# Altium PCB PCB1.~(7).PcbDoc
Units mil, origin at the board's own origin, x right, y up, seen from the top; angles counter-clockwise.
Board outline 2756 x 2756 mil, 4 copper layers (Top Layer, Internal Plane 1, Internal Plane 2, Bottom Layer), stack 18.2 mil thick; 11 components, 12 nets, 54 pads, 0 vias.
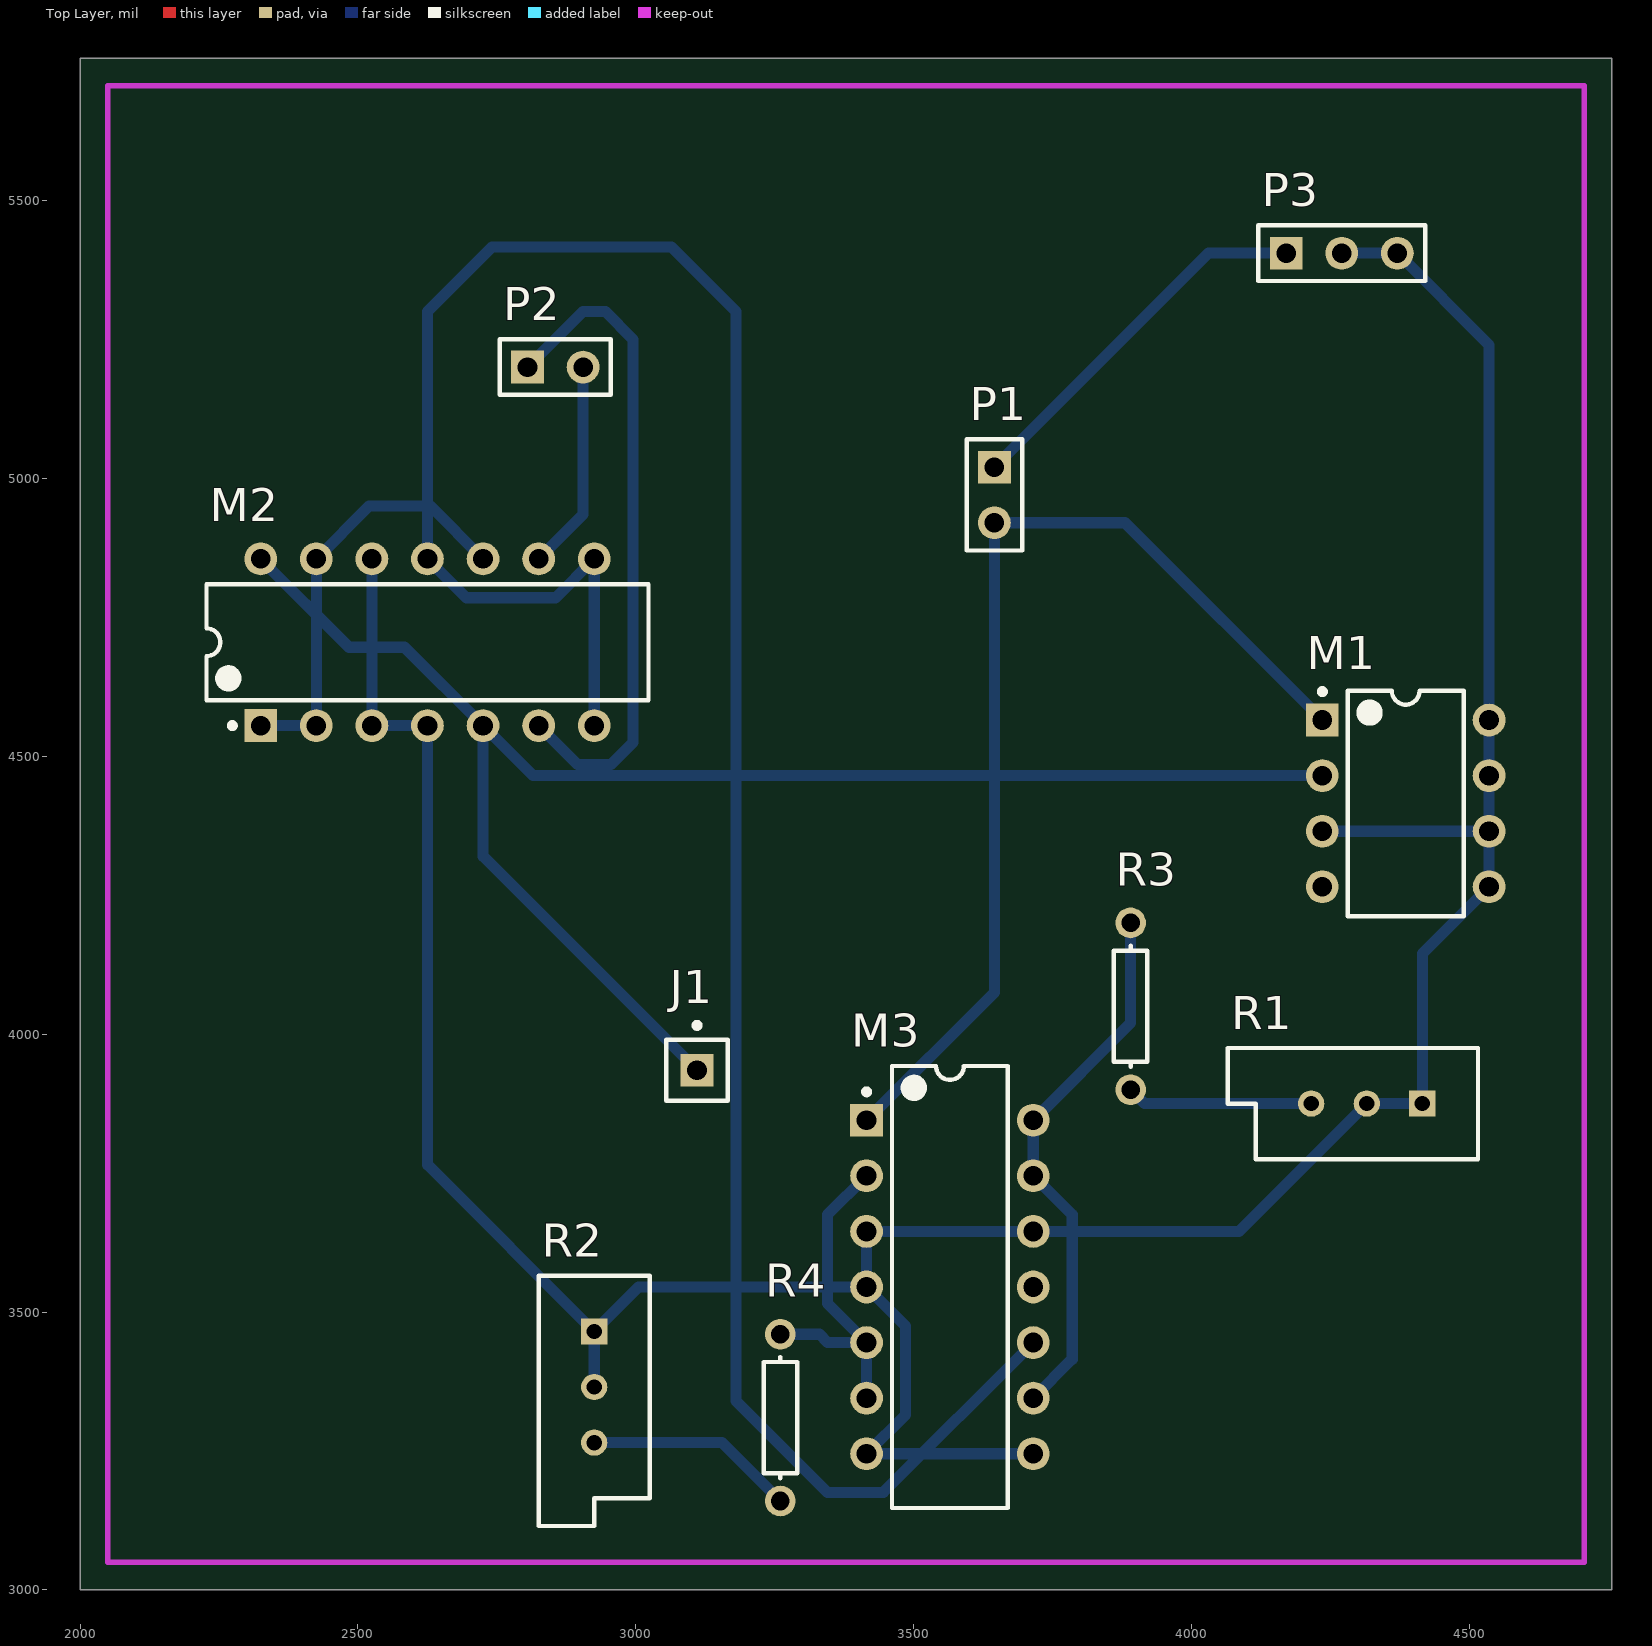
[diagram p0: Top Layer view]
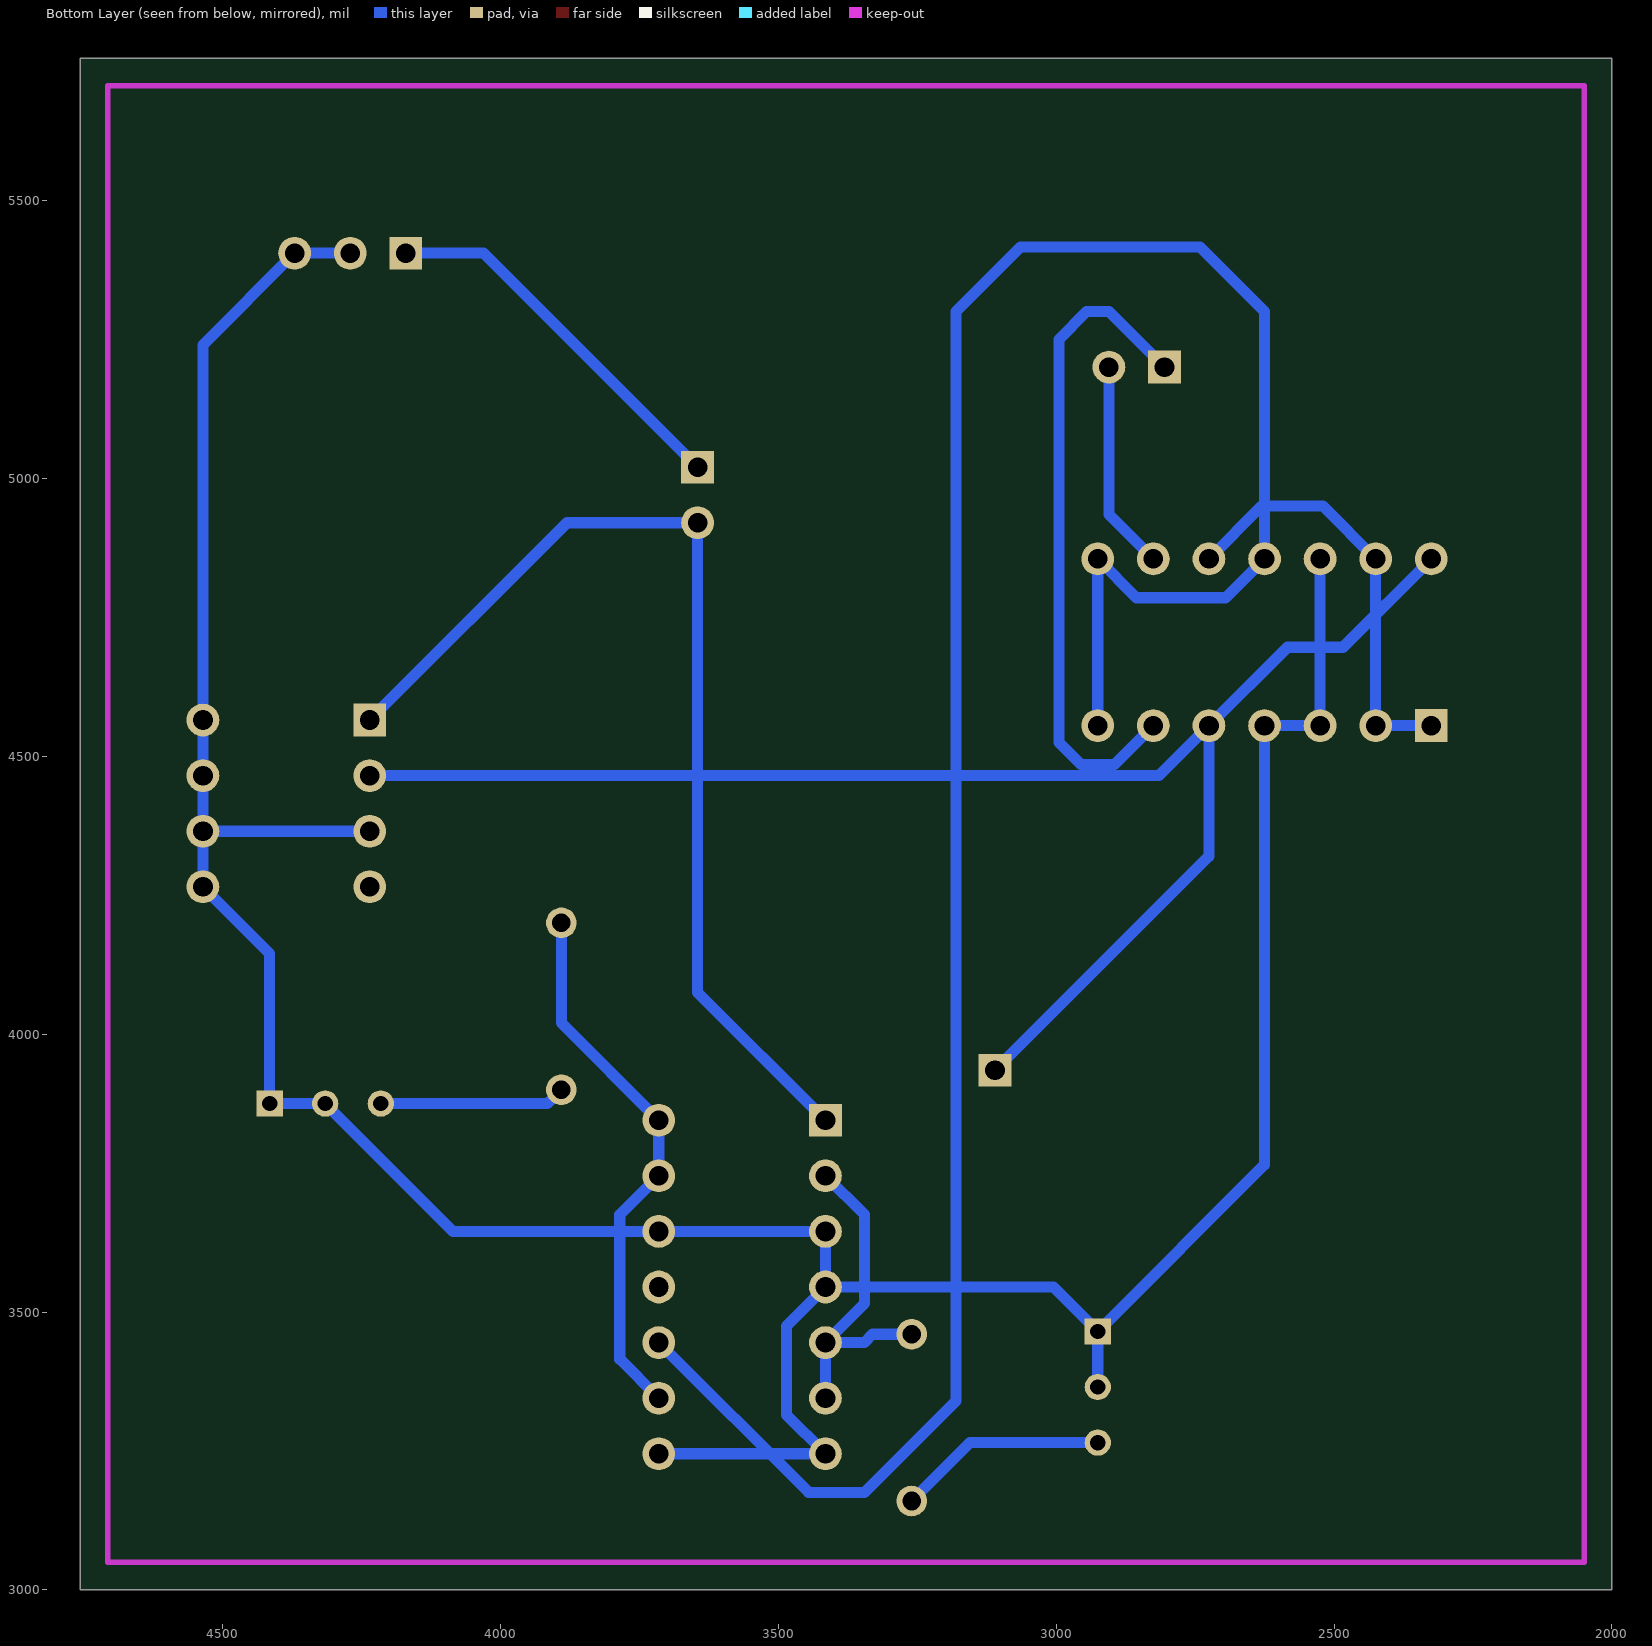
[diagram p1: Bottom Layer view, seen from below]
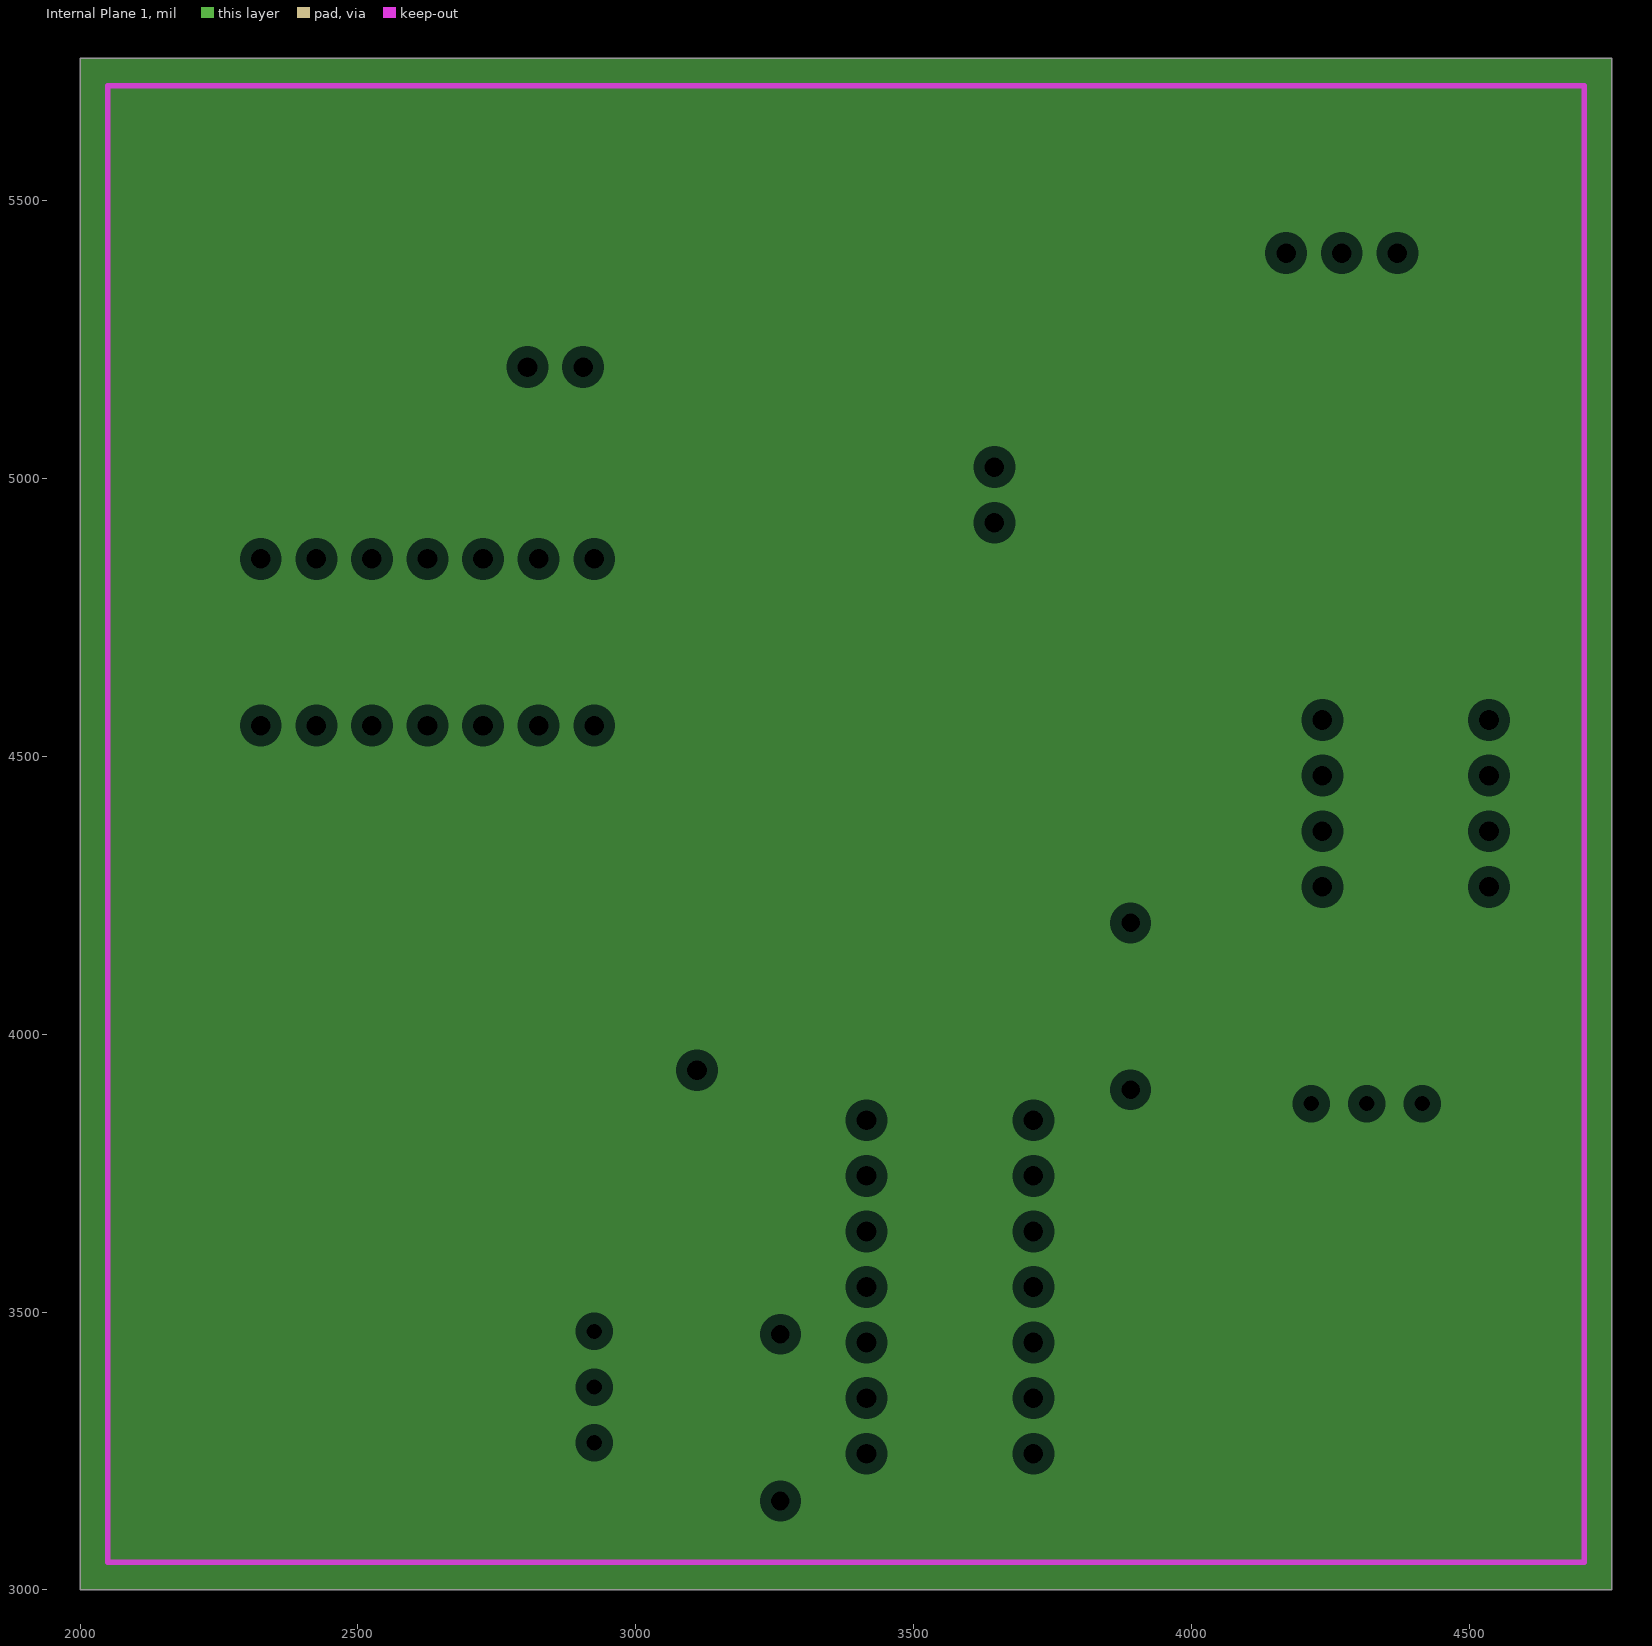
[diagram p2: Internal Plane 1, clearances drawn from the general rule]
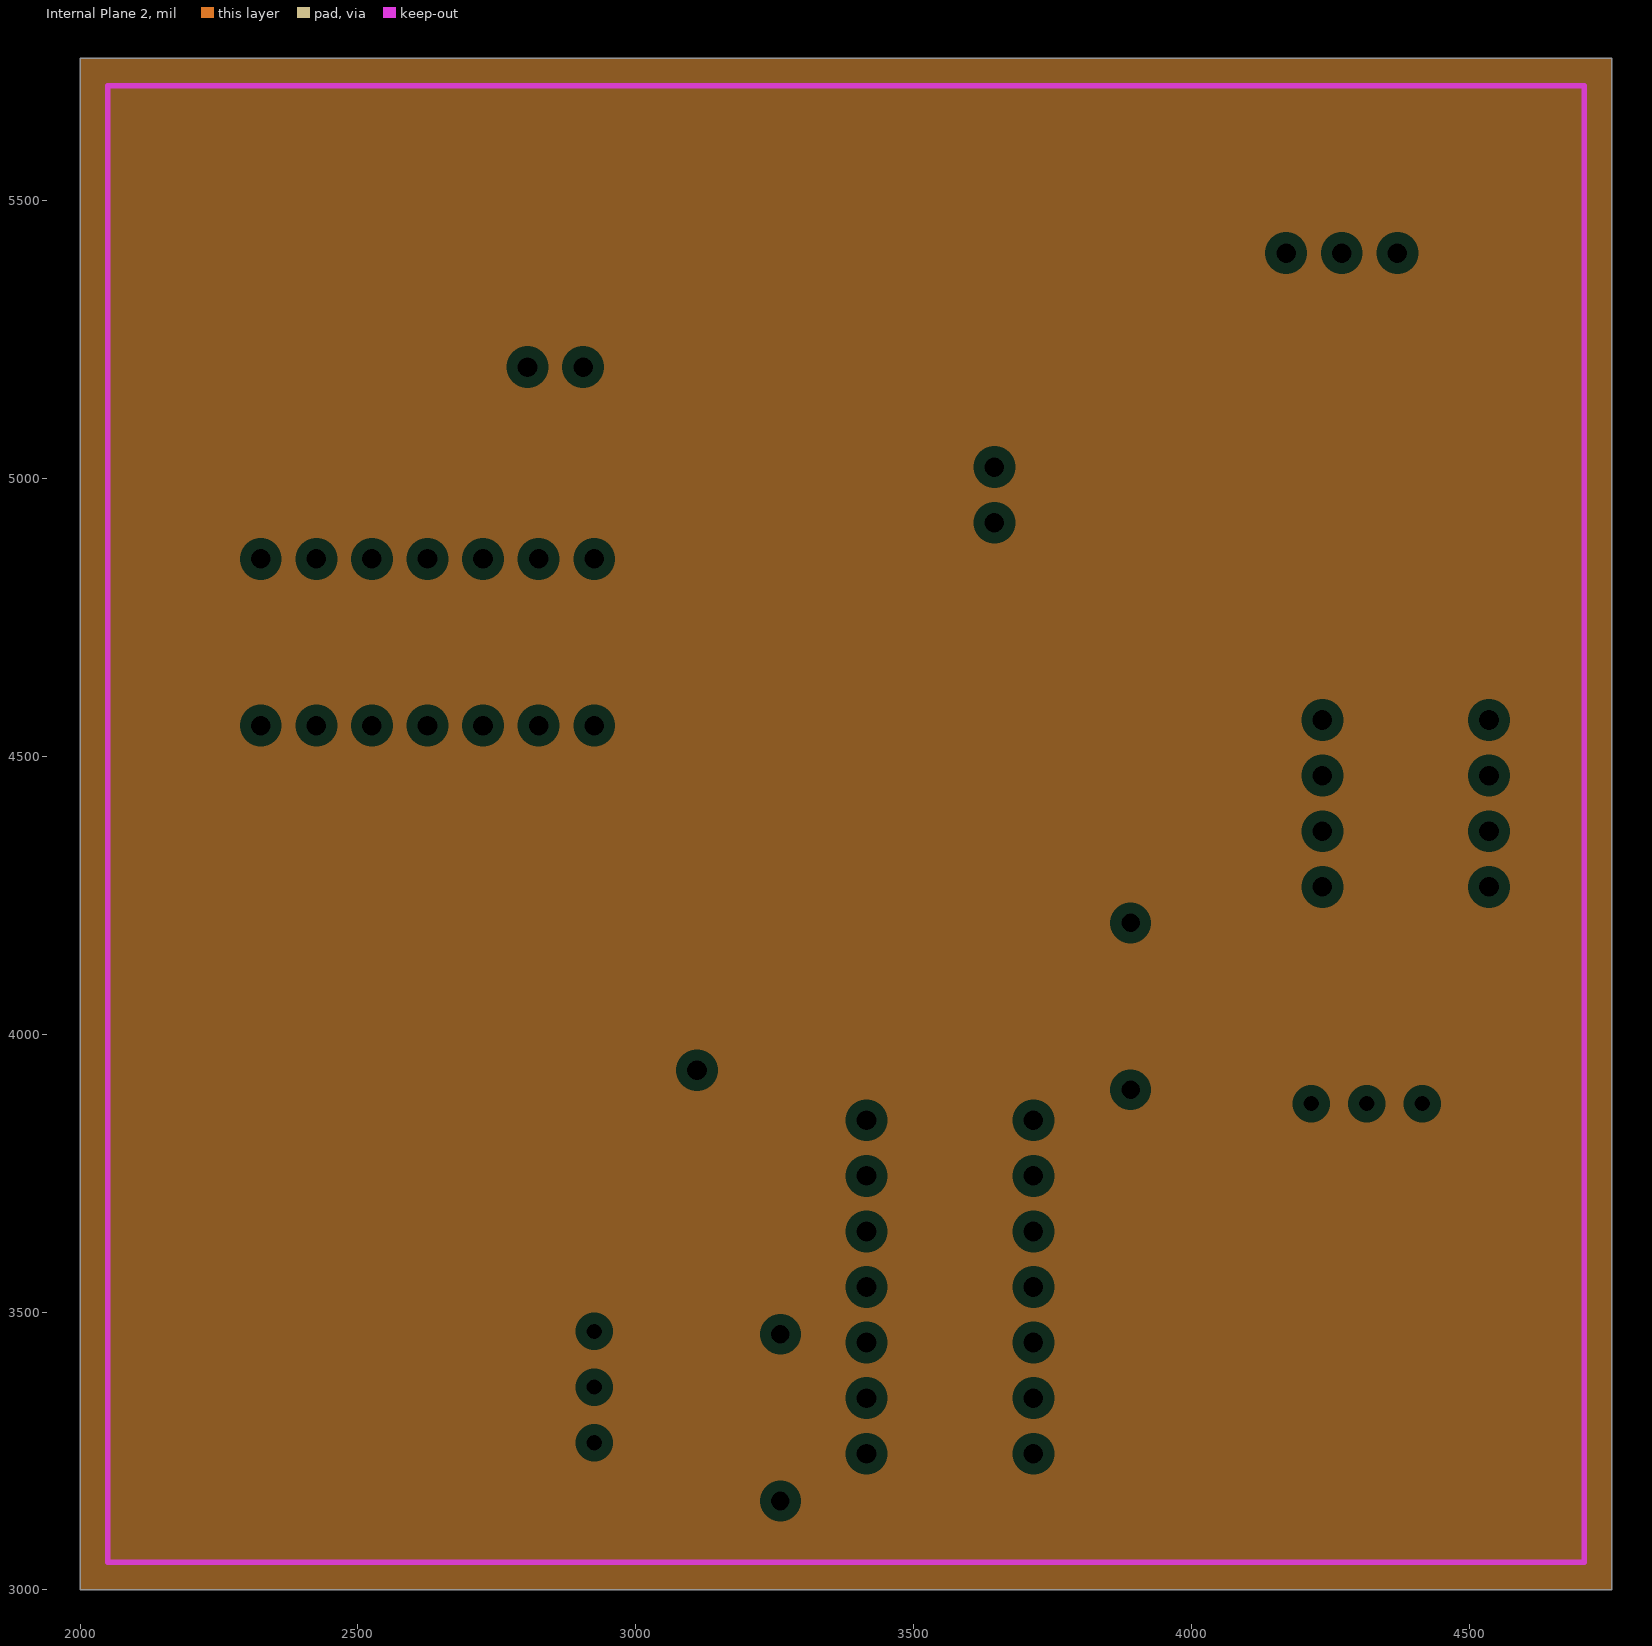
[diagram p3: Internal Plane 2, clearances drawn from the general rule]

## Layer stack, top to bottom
Top Solder: solder mask 0.4, Solder Resist, Dk 3.5
Top Layer: signal copper 1.4
Internal Plane 1: plane copper 1.4
Internal Plane 2: plane copper 1.4
Dielectric 1: dielectric 12.6, FR-4, Dk 4.8
Bottom Layer: signal copper 1.4
Bottom Solder: solder mask 0.4, Solder Resist, Dk 3.5

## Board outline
2000,3000 4756,3000 4756,5756 2000,5756

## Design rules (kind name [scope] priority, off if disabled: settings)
Clearance [All] p1: gap=30
PlaneClearance [All] p1: clearance=20
PlaneConnect [All] p1: planeconnectstyle=Relief reliefexpansion=20 reliefentries=4 reliefconductorwidth=10 reliefairgap=10
PolygonConnect [All] p1: connectstyle=Relief reliefconductorwidth=10 reliefentries=4 polygonreliefangle="90 Angle" airgapwidth=10
RoutingVias [All] p1: holewidth=32 width=62 viastyle="Through Hole" minholewidth=28 minwidth=50 maxholewidth=28 maxwidth=50
SolderMaskExpansion [All] p1: expansion=4
Width [All] p1: maxlimit=20 minlimit=20 preferedwidth=20
28 further rules are at their usual default settings.

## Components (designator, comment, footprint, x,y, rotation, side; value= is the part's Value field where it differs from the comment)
J1 "Socket" PIN1 3110,3935 r0 top
M1 "ALD1117" DIP-8 4385,4415 r0 top
M2 "ALD1105" DIP-14 2625,4705 r90 top
M3 "ALD1106" DIP-14 3565,3545 r0 top
P1 "Header 2" HDR1X2 3645,5020 r270 top
P2 "Header 2" HDR1X2 2805,5200 r0 top
P3 "Header 3" HDR1X3 4170,5405 r0 top
R1 "RPot" VR5 4315,3875 r180 top
R2 "RPot" VR5 2925,3365 r270 top
R3 "Res1" AXIAL-0.3 3890,4050 r270 top
R4 "Res1" AXIAL-0.3 3260,3310 r270 top

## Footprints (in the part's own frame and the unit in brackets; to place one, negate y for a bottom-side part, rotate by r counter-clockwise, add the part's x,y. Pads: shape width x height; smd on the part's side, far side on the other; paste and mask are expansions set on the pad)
AXIAL-0.3 [mm] "Axial Device, Thru-Hole; 2 Leads; 0.3 in Pin Spacing"
  round 1.4 hole 0.85: 1(-3.81,0) 2(3.81,0)
  silkscreen extent -2.77,-0.76 2.77,0.76
DIP-8 [mm] "DIP, 8-Pin, Row Spacing 7.62 mm, Pitch 2.54 mm"
  rect 1.5x1.5 hole 0.9: 1(-3.81,3.81)
  round 1.5 hole 0.9: 2(-3.81,1.27) 3(-3.81,-1.27) 4(-3.81,-3.81) 5(3.81,-3.81) 6(3.81,-1.27) 7(3.81,1.27) 8(3.81,3.81)
  silkscreen extent -3.93,-5.15 2.65,5.23, body extent -3.6,-5.15 3.6,5.15, height 5.33
DIP-14 [mm] "DIP, 14-Pin, Row Spacing 7.62 mm, Pitch 2.54 mm"
  rect 1.5x1.5 hole 0.9: 1(-3.81,7.62)
  round 1.5 hole 0.9: 2(-3.81,5.08) 3(-3.81,2.54) 4(-3.81,0) 5(-3.81,-2.54) 6(-3.81,-5.08) 7(-3.81,-7.62) 8(3.81,-7.62) 9(3.81,-5.08) 10(3.81,-2.54) 11(3.81,0) 12(3.81,2.54) 13(3.81,5.08) 14(3.81,7.62)
  silkscreen extent -3.93,-10.1 2.65,10.1, body extent -3.6,-10.1 3.6,10.1, height 5.08
HDR1X2 [mm] "Connector; Header; 2 Position"
  rect 1.5x1.5 hole 0.9: 1(0,0)
  round 1.5 hole 0.9: 2(2.54,0)
  silkscreen extent -1.27,-1.27 3.81,1.27
HDR1X3 [mm] "Connector; Header; 3 Position"
  rect 1.5x1.5 hole 0.9: 1(0,0)
  round 1.5 hole 0.9: 2(2.54,0) 3(5.08,0)
  silkscreen extent -1.27,-1.27 6.35,1.27
PIN1 [mm] "Connector; Plug"
  rect 1.5x1.5 hole 0.9: 1(0,0)
  silkscreen extent -1.4,-1.4 1.4,2.17
VR5 [mm] "Thru-Hole; 3 Leads"
  rect 1.2x1.2 hole 0.7: 1(-2.54,0)
  round 1.2 hole 0.7: 2(0,0) 3(2.54,0)
  silkscreen extent -5.08,-2.54 6.35,2.54

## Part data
M1: "Dual P-channel matched MOSFET array"
M2: "Dual P-channel and dual N-channel matched MOSFET array"
M3: "Quad N-channel matched MOSFET array"
P1 P2: "Header, 2-Pin"
P3: "Header, 3-Pin"
R1 R2: "Potentiometer"
R3 R4: "Resistor"

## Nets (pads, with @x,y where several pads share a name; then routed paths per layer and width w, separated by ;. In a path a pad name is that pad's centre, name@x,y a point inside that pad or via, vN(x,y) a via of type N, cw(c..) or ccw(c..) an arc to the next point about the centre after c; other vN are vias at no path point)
GND: P1.1 P3.1 | length 684.5
  Bottom Layer w20: P1.1 4030,5405 P3.1
NetJ1_1: J1.1 M1.2 M2.5 M2.14 | length 2851
  Bottom Layer w20: M2.14 2484,4696 2584,4696 M2.5 ; J1.1 2725,4320 M2.5 ; M1.2 2815,4465 M2.5
NETLABEL5: M2.6 P2.1 | length 1192.7
  Bottom Layer w20: P2.1 2905,5300 2945,5300 2995,5250 2995,4525 2955,4485 2895,4485 M2.6
NETLABEL7: M2.9 P2.2 | length 378.1
  Bottom Layer w20: M2.9 2905,4935 P2.2
NETLABEL9: M1.3 M1.5 M1.6 M1.7 M1.8 M2.3 M2.4 M2.12 M3.3 M3.4 M3.7 M3.8 M3.12 P3.2 P3.3 R1.1 R1.2 R2.1 R2.2 | length 6138.7
  Bottom Layer w20: M2.12 M2.3 M2.4 2625,3765 R2.1 ; R2.2 R2.1 ; M3.8 M3.7 3485,3315 3485,3475 M3.4 ; M1.3 M1.6 ; P3.2 P3.3 4535,5240 M1.8 M1.7 M1.6 ; R2.1 3005,3545 M3.4 ; M3.4 M3.3 M3.12 4085,3645 R1.2 R1.1 4415,4145 M1.5 M1.6
NetM1_1: M1.1 M3.1 P1.2 | length 1907.3
  Bottom Layer w20: M3.1 3645,4075 P1.2 3880,4920 M1.1
NetM2_1: M2.1 M2.2 M2.10 M2.13 | length 778.7
  Bottom Layer w20: M2.1 M2.2 M2.13 2520,4950 2630,4950 M2.10
NetM2_7: M2.7 M2.8 M2.11 M3.10 | length 4429.3
  Bottom Layer w20: M2.7 M2.8 2855,4785 2695,4785 M2.11 2625,5300 2741,5416 3064,5416 3180,5300 3180,3340 3345,3175 3445,3175 M3.10
NetM3_2: M3.2 M3.5 M3.6 R4.1 | length 619.2
  Bottom Layer w20: R4.1 3330,3460 3345,3445 M3.5 ; M3.6 M3.5 ; M3.2 3345,3675 3345,3515 M3.5
NetM3_9: M3.9 M3.13 M3.14 R3.1 | length 985.5
  Bottom Layer w20: M3.9 3785,3415 3785,3675 M3.13 M3.14 3890,4020 R3.1
NetR1_3: R1.3 R3.2 | length 335.4
  Bottom Layer w20: R3.2 3915,3875 R1.3
NetR2_3: R2.3 R4.2 | length 378.5
  Bottom Layer w20: R2.3 3155,3265 R4.2
pads on no net: M1.4 M3.11

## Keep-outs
Keep-Out Layer:
  lines w10: 2050,3050 2050,5706 4706,5706 4706,3050 2050,3050

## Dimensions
2050,3050 to 2050,5706 on Mechanical 1
2050,3050 to 4706,3050 on Mechanical 1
